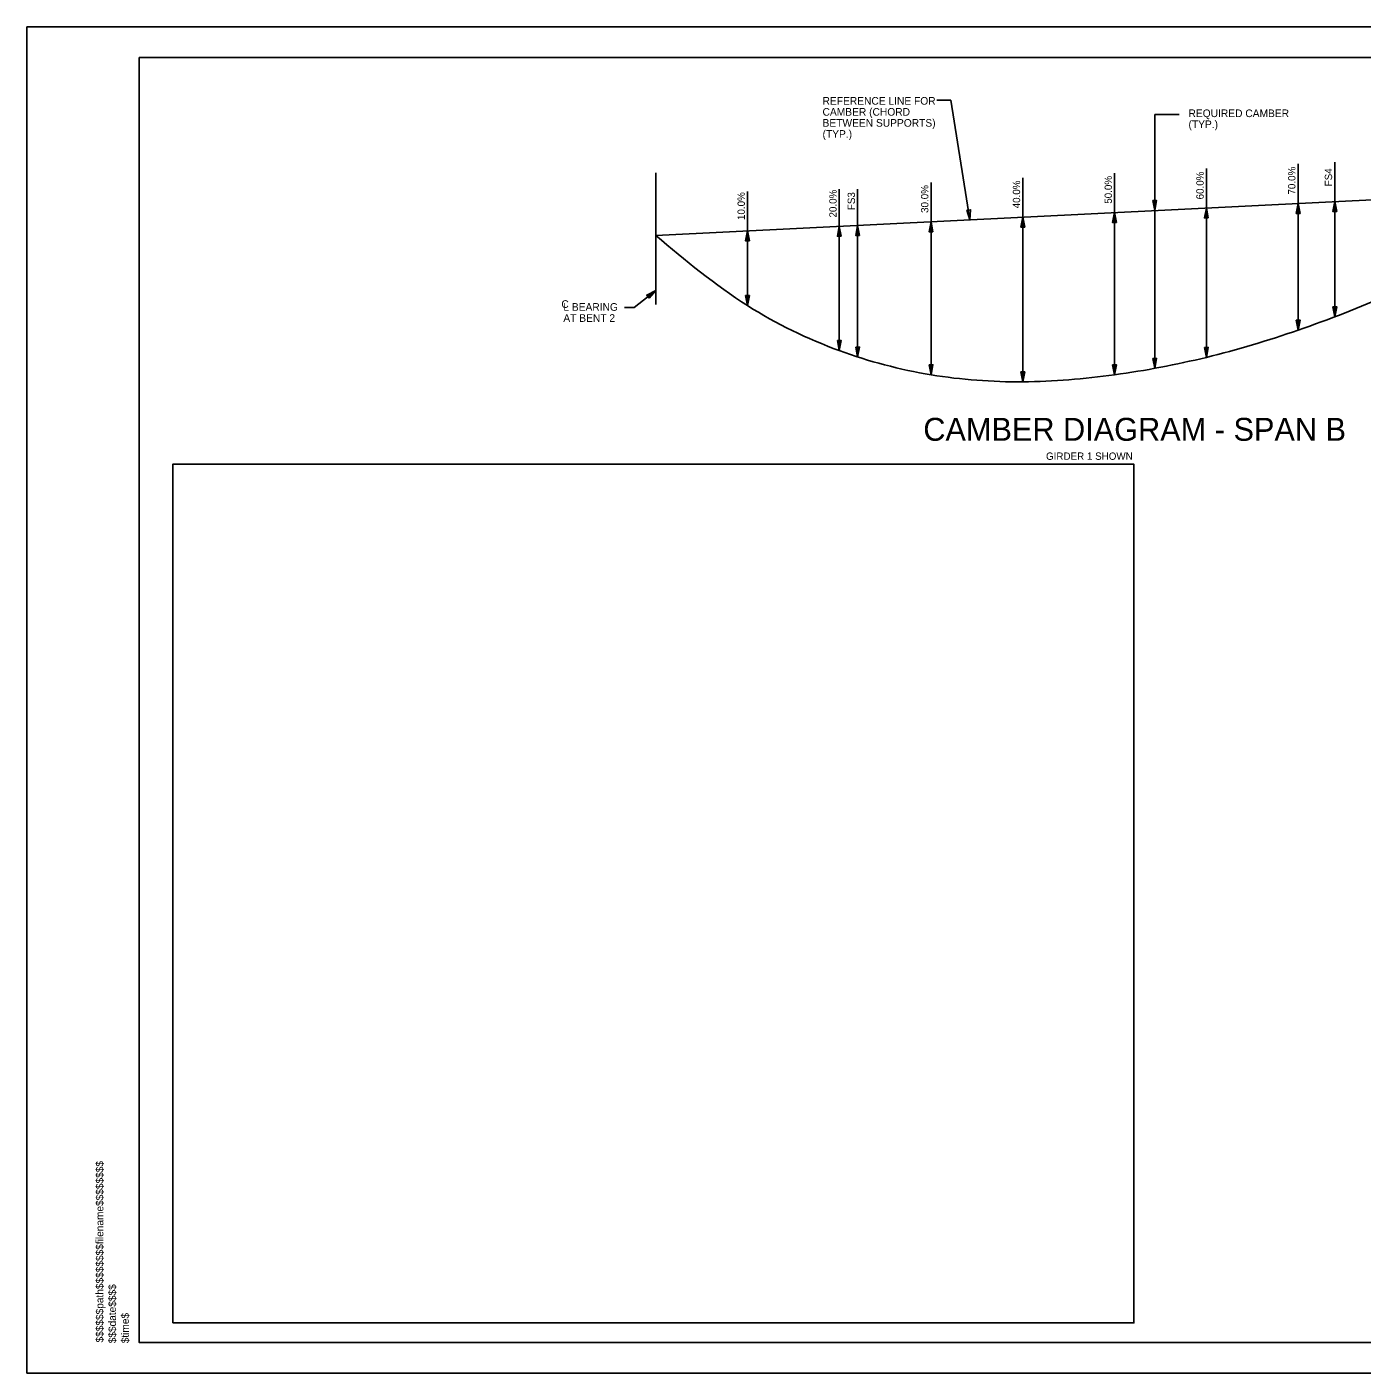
# Model space of a CAD drawing. Extents: x -125.5 to -89.4, y -5.1 to 16.9.
# Drawn here: x -125.53 to -103.71, y -5.07 to 16.93 of the extents above; entities that cross this region are included whole.
import ezdxf

# ---------------------------------------------------------------- set-up
doc = ezdxf.new("R2010")
doc.units = 0
for name, color, linetype in [('BR_AUTO DIMENSION', 7, 'Continuous'), ('BR_BORDER LINES', 7, 'Continuous'), ('BR_CENTER LINES', 7, 'Continuous'), ('BR_TABLE LINES', 7, 'Continuous'), ('BR_TEXT', 7, 'Continuous'), ('Level 31', 7, 'Continuous'), ('RD_SHT_ID', 7, 'Continuous')]:
    doc.layers.add(name, color=color, linetype=linetype)

msp = doc.modelspace()

# ---------------------------------------------------------------- linework, layer by layer
at = {"layer": 'BR_AUTO DIMENSION'}
for p, q in [((-110.66, 15.736), (-110.431, 15.736)), ((-110.431, 15.736), (-110.117, 13.781)), ((-107.098, 15.505), (-106.696, 15.505)), ((-107.098, 11.355), (-107.098, 15.505)), ((-115.605, 12.347), (-115.253, 12.627)), ((-115.765, 12.347), (-115.605, 12.347))]:
    msp.add_line(p, q, dxfattribs=at)
for points in [[(-107.129, 14.095), (-107.098, 13.932), (-107.066, 14.095)], [(-110.169, 13.938), (-110.117, 13.781), (-110.107, 13.946)], [(-107.722, 13.737), (-107.753, 13.899), (-107.785, 13.737)], [(-106.222, 13.812), (-106.253, 13.974), (-106.285, 13.812)], [(-104.722, 13.887), (-104.753, 14.049), (-104.785, 13.887)], [(-104.122, 13.917), (-104.153, 14.079), (-104.185, 13.917)], [(-112.222, 13.512), (-112.253, 13.674), (-112.285, 13.512)], [(-111.922, 13.527), (-111.953, 13.689), (-111.985, 13.527)], [(-110.722, 13.587), (-110.753, 13.749), (-110.785, 13.587)], [(-109.222, 13.662), (-109.253, 13.824), (-109.285, 13.662)], [(-113.722, 13.437), (-113.753, 13.599), (-113.785, 13.437)], [(-115.362, 12.503), (-115.253, 12.627), (-115.401, 12.552)], [(-113.785, 12.542), (-113.753, 12.379), (-113.722, 12.542)], [(-104.185, 12.36), (-104.153, 12.197), (-104.122, 12.36)], [(-104.785, 12.142), (-104.753, 11.979), (-104.722, 12.142)], [(-112.285, 11.807), (-112.253, 11.644), (-112.222, 11.807)], [(-111.985, 11.702), (-111.953, 11.54), (-111.922, 11.702)], [(-106.285, 11.697), (-106.253, 11.534), (-106.222, 11.697)], [(-107.129, 11.517), (-107.098, 11.355), (-107.066, 11.517)], [(-110.785, 11.412), (-110.753, 11.249), (-110.722, 11.412)], [(-109.285, 11.297), (-109.253, 11.134), (-109.222, 11.297)], [(-107.785, 11.412), (-107.753, 11.249), (-107.722, 11.412)]]:
    msp.add_lwpolyline(points, close=True, dxfattribs=at)
at = {"layer": 'BR_BORDER LINES'}
for p, q in [((-90.033, 16.434), (-123.699, 16.434)), ((-123.699, -4.566), (-123.699, 16.434)), ((-123.699, -4.566), (-90.033, -4.566))]:
    msp.add_line(p, q, dxfattribs=at)
at = {"layer": 'BR_CENTER LINES'}
msp.add_line((-115.253, 12.4), (-115.253, 14.55), dxfattribs=at)
at = {"layer": 'BR_TABLE LINES'}
for p, q in [((-107.753, 11.249), (-107.753, 14.544)), ((-106.253, 11.534), (-106.253, 14.619)), ((-104.753, 11.979), (-104.753, 14.694)), ((-104.153, 12.197), (-104.153, 14.724)), ((-110.753, 11.249), (-110.753, 14.394)), ((-109.253, 11.134), (-109.253, 14.469)), ((-100.24, 14.275), (-115.253, 13.524)), ((-113.753, 12.379), (-113.753, 14.244)), ((-112.253, 11.644), (-112.253, 14.285)), ((-111.953, 11.54), (-111.953, 14.285))]:
    msp.add_line(p, q, dxfattribs=at)
for points in [[(-123.699, 16.434), (-90.033, 16.434), (-90.033, -4.566), (-123.699, -4.566)], [(-123.148, -4.246), (-107.438, -4.246), (-107.438, 9.787), (-123.148, 9.787)]]:
    msp.add_lwpolyline(points, close=True, dxfattribs=at)
msp.add_spline([(-115.253, 13.524), (-113.753, 12.379), (-112.253, 11.644), (-110.753, 11.249), (-109.253, 11.134), (-107.753, 11.249), (-106.253, 11.534), (-104.753, 11.979), (-103.253, 12.564), (-101.753, 13.309), (-100.24, 14.275)], degree=3, dxfattribs=at)
at = {"layer": 'Level 31'}
msp.add_lwpolyline([(-125.533, -5.066), (-89.533, -5.066), (-89.533, 16.934), (-125.533, 16.934)], close=True, dxfattribs=at)

# ---------------------------------------------------------------- texts
at = {"layer": 'BR_AUTO DIMENSION'}
for s, p in [('REFERENCE LINE FOR', (-112.527, 15.663)), ('CAMBER (CHORD', (-112.527, 15.483)), ('BETWEEN SUPPORTS)', (-112.527, 15.303)), ('(TYP.)', (-106.545, 15.28)), ('REQUIRED CAMBER', (-106.545, 15.46)), ('(TYP.)', (-112.527, 15.122)), ('C', (-116.796, 12.342)), ('L BEARING', (-116.764, 12.295)), ('AT BENT 2', (-116.764, 12.114))]:
    msp.add_text(s, height=0.125, dxfattribs=at).set_placement(p)
at = {"layer": 'BR_TEXT'}
for s, p in [('60.0%', (-106.297, 14.115)), ('70.0%', (-104.797, 14.194)), ('FS4', (-104.197, 14.329)), ('30.0%', (-110.797, 13.894)), ('40.0%', (-109.297, 13.969)), ('50.0%', (-107.797, 14.044)), ('10.0%', (-113.797, 13.778)), ('20.0%', (-112.297, 13.819)), ('FS3', (-111.997, 13.939))]:
    msp.add_text(s, height=0.12, rotation=90, dxfattribs=at).set_placement(p)
for s, height, p in [('CAMBER DIAGRAM - SPAN B', 0.375, (-110.88, 10.17)), ('GIRDER 1 SHOWN', 0.12, (-108.874, 9.859))]:
    msp.add_text(s, height=height, dxfattribs=at).set_placement(p)
at = {"layer": 'RD_SHT_ID'}
for s, height, p in [('$$$$$$path$$$$$$$$filename$$$$$$$$', 0.12347, (-124.283, -4.566)), ('$$$date$$$$', 0.12347, (-124.077, -4.579)), ('$time$', 0.1235, (-123.866, -4.579))]:
    msp.add_text(s, height=height, rotation=90, dxfattribs=at).set_placement(p)

doc.saveas('drawing.dxf')
